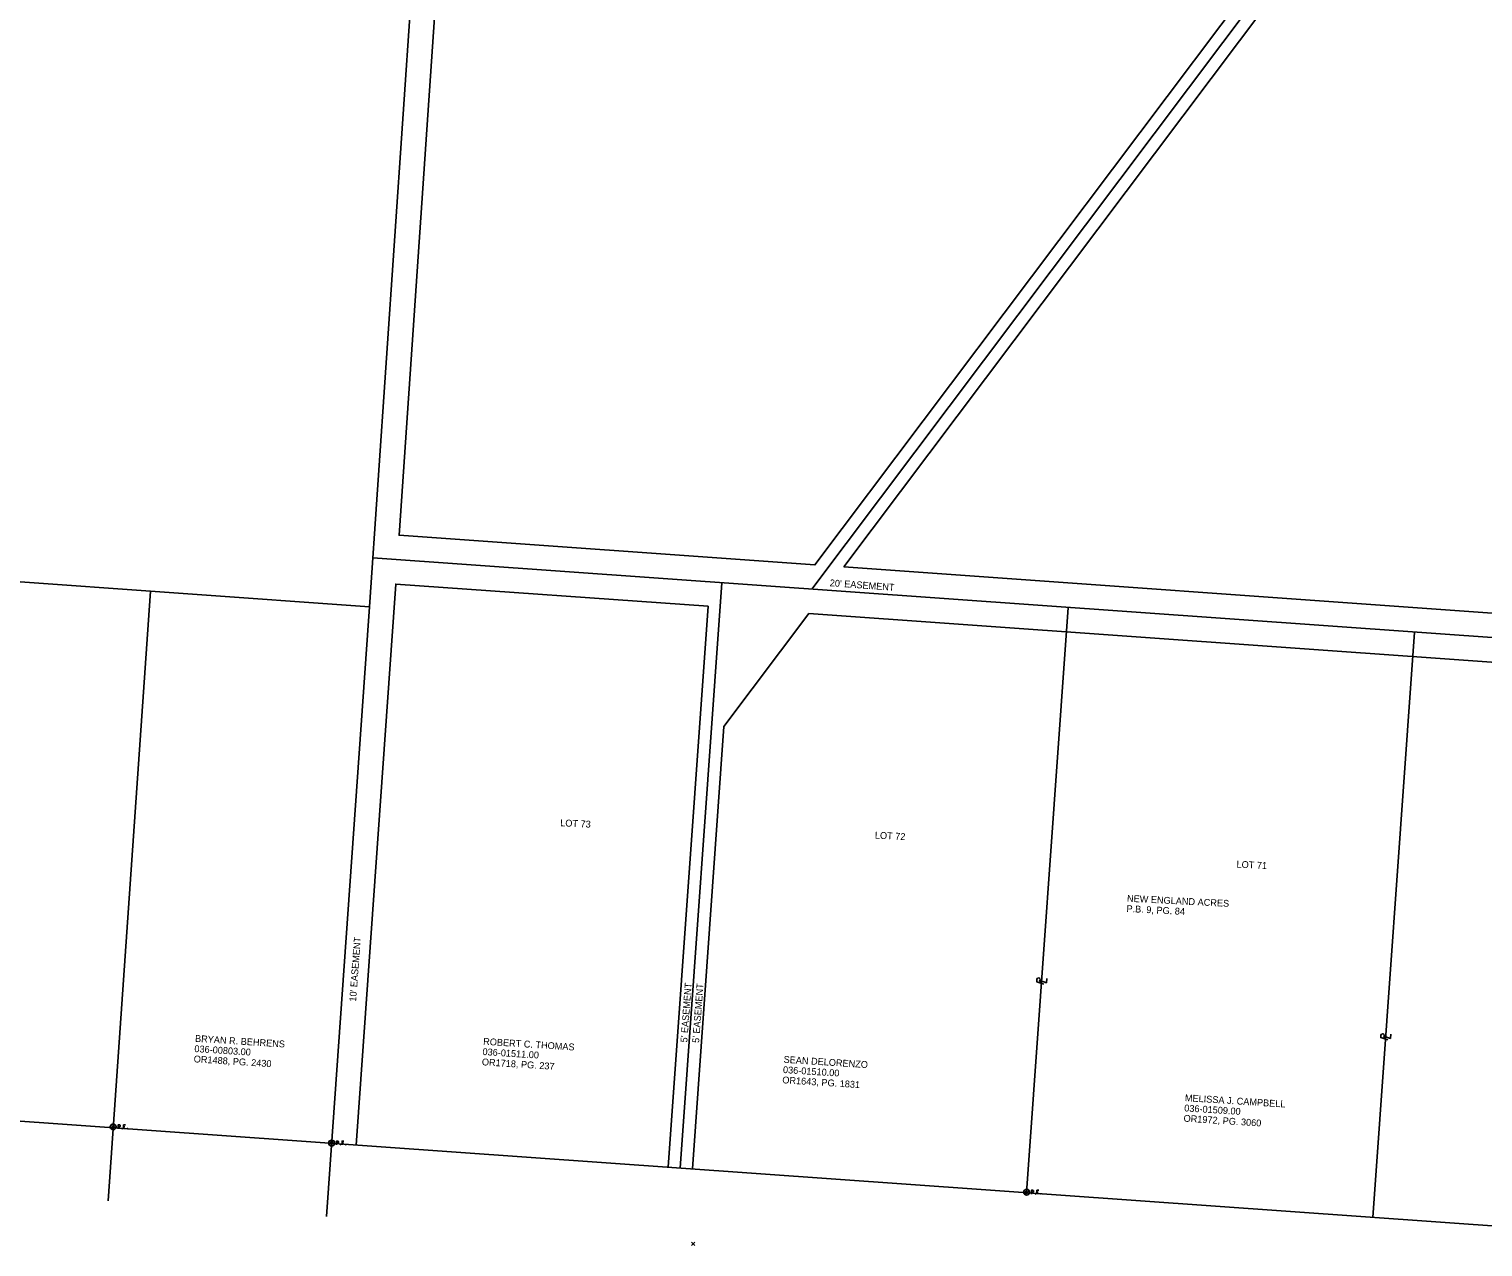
# Model space of a CAD drawing. Extents: x 1898254 to 1901377, y 701554 to 704886.
# Drawn here: x 1898855 to 1899450, y 703277 to 703775 of the extents above; entities that cross this region are included whole.
import ezdxf

# ---------------------------------------------------------------- set-up
doc = ezdxf.new("R2010")
doc.units = 0
for name, color, linetype in [('DV_X_Property_Line', 7, 'Continuous'), ('DV_X_Text', 7, 'Continuous'), ('RW_X_Esmt_General', 7, 'Continuous'), ('RW_X_Esmt_U', 7, 'Continuous'), ('RW_X_Fee_RW', 7, 'Continuous'), ('SC_Scratch2', 7, 'Continuous'), ('SC_Scratch5', 7, 'Continuous'), ('SV_X_Mon_Cells_Found', 7, 'Continuous'), ('SV_X_Random_Point', 7, 'Continuous')]:
    doc.layers.add(name, color=color, linetype=linetype)

msp = doc.modelspace()

# ---------------------------------------------------------------- linework, layer by layer
at = {"layer": 'DV_X_Property_Line'}
for p, q in [((1899357.75, 703788.77), (1899175.29, 703546.06)), ((1898994.39, 703538.88), (1898645.43, 703563.69)), ((1899563.1, 703518.49), (1898995.75, 703558.83)), ((1898887.4, 703295.86), (1898904.77, 703545.25)), ((1899138.49, 703548.68), (1899121.47, 703309.29)), ((1898994.39, 703538.88), (1898976.73, 703289.5)), ((1899280.14, 703538.61), (1899263.11, 703299.21)), ((1899421.78, 703528.54), (1899404.75, 703289.14)), ((1899268.59, 703385.02), (1899268.68, 703386.32)), ((1899269.27, 703385.78), (1899269.27, 703385.78)), ((1899409.33, 703362.22), (1899409.42, 703363.52)), ((1899410.01, 703362.98), (1899410.01, 703362.98))]:
    msp.add_line(p, q, dxfattribs=at)
for points in [[(1899270.15, 703384.49), (1899267.25, 703385.48), (1899267.32, 703386.51)], [(1899268.33, 703386.11), (1899271.22, 703385.11), (1899271.35, 703386.86)], [(1899410.88, 703361.69), (1899407.98, 703362.68), (1899408.06, 703363.71)], [(1899409.07, 703363.31), (1899411.96, 703362.31), (1899412.08, 703364.06)]]:
    msp.add_lwpolyline(points, dxfattribs=at)
for centre in [(1899267.99, 703386.36), (1899408.73, 703363.56)]:
    msp.add_arc(centre, 0.69, 356.4035, 167.26062, dxfattribs=at)
at = {"layer": 'DV_X_Text'}
msp.add_line((1899086.29, 704885.75), (1898994.39, 703538.88), dxfattribs=at)
at = {"layer": 'RW_X_Esmt_General'}
msp.add_line((1899139.33, 703489.9), (1899126.46, 703308.93), dxfattribs=at)
at = {"layer": 'RW_X_Esmt_U'}
for q in [(1899361.75, 703785.77), (1899563.81, 703528.46)]:
    msp.add_line((1899188.39, 703555.16), q, dxfattribs=at)
for points in [[(1899096.27, 704885.07), (1899006.4, 703568.1), (1899176.51, 703556), (1899353.75, 703791.78)], [(1898988.83, 703318.72), (1899005.04, 703548.15), (1899132.8, 703539.06), (1899116.48, 703309.64)], [(1899139.33, 703489.9), (1899174.08, 703536.13), (1899562.39, 703508.51)]]:
    msp.add_lwpolyline(points, dxfattribs=at)
at = {"layer": 'RW_X_Fee_RW'}
msp.add_line((1898630.14, 703344.22), (1899526.13, 703280.51), dxfattribs=at)
at = {"layer": 'SC_Scratch2'}
msp.add_circle((1899815.76, 703229.84), 1561.35, dxfattribs=at)
at = {"layer": 'SC_Scratch5'}
msp.add_line((1898630.14, 703344.22), (1899526.13, 703280.51), dxfattribs=at)
at = {"layer": 'SV_X_Mon_Cells_Found'}
for points in [[(1898891.51, 703325.34), (1898891.51, 703326.94), (1898892.04, 703326.94), (1898892.09, 703326.93), (1898892.17, 703326.91), (1898892.2, 703326.88), (1898892.24, 703326.86), (1898892.28, 703326.79), (1898892.31, 703326.73), (1898892.34, 703326.63), (1898892.34, 703326.48), (1898892.32, 703326.43), (1898892.3, 703326.35), (1898892.26, 703326.26), (1898892.21, 703326.23), (1898892.18, 703326.2), (1898892.13, 703326.18), (1898892.04, 703326.16), (1898891.51, 703326.16)], [(1898893.15, 703325.56), (1898893.21, 703325.56), (1898893.24, 703325.53), (1898893.27, 703325.48), (1898893.27, 703325.42), (1898893.24, 703325.37), (1898893.21, 703325.34), (1898893.15, 703325.34), (1898893.12, 703325.37), (1898893.09, 703325.42), (1898893.09, 703325.48), (1898893.12, 703325.53), (1898893.15, 703325.56)], [(1898894.52, 703326.94), (1898893.76, 703326.94), (1898893.76, 703325.34)], [(1898893.76, 703326.16), (1898894.3, 703326.16)], [(1898895.3, 703325.56), (1898895.36, 703325.56), (1898895.39, 703325.53), (1898895.42, 703325.48), (1898895.42, 703325.42), (1898895.39, 703325.37), (1898895.36, 703325.34), (1898895.3, 703325.34), (1898895.27, 703325.37), (1898895.23, 703325.42), (1898895.23, 703325.48), (1898895.27, 703325.53), (1898895.3, 703325.56)], [(1898980.86, 703318.73), (1898980.86, 703320.33), (1898981.39, 703320.33), (1898981.44, 703320.32), (1898981.52, 703320.29), (1898981.55, 703320.27), (1898981.58, 703320.24), (1898981.63, 703320.18), (1898981.66, 703320.12), (1898981.68, 703320.02), (1898981.68, 703319.87), (1898981.67, 703319.82), (1898981.65, 703319.74), (1898981.61, 703319.65), (1898981.56, 703319.61), (1898981.53, 703319.59), (1898981.47, 703319.56), (1898981.39, 703319.55), (1898980.86, 703319.55)], [(1898982.5, 703318.95), (1898982.56, 703318.95), (1898982.59, 703318.92), (1898982.62, 703318.87), (1898982.62, 703318.81), (1898982.59, 703318.76), (1898982.56, 703318.73), (1898982.5, 703318.73), (1898982.47, 703318.76), (1898982.43, 703318.81), (1898982.43, 703318.87), (1898982.47, 703318.92), (1898982.5, 703318.95)], [(1898983.87, 703320.33), (1898983.11, 703320.33), (1898983.11, 703318.73)], [(1898983.11, 703319.55), (1898983.65, 703319.55)], [(1898984.65, 703318.95), (1898984.7, 703318.95), (1898984.74, 703318.92), (1898984.77, 703318.87), (1898984.77, 703318.81), (1898984.74, 703318.76), (1898984.7, 703318.73), (1898984.65, 703318.73), (1898984.62, 703318.76), (1898984.58, 703318.81), (1898984.58, 703318.87), (1898984.62, 703318.92), (1898984.65, 703318.95)], [(1899265.12, 703298.62), (1899265.12, 703300.22), (1899265.65, 703300.22), (1899265.71, 703300.2), (1899265.79, 703300.18), (1899265.82, 703300.15), (1899265.85, 703300.13), (1899265.9, 703300.07), (1899265.93, 703300), (1899265.95, 703299.9), (1899265.95, 703299.75), (1899265.94, 703299.7), (1899265.92, 703299.62), (1899265.87, 703299.54), (1899265.83, 703299.5), (1899265.8, 703299.47), (1899265.74, 703299.45), (1899265.65, 703299.44), (1899265.12, 703299.44)], [(1899268.13, 703300.22), (1899267.37, 703300.22), (1899267.37, 703298.62)], [(1899267.37, 703299.44), (1899267.91, 703299.44)], [(1899266.77, 703298.83), (1899266.82, 703298.83), (1899266.85, 703298.81), (1899266.89, 703298.76), (1899266.89, 703298.69), (1899266.85, 703298.64), (1899266.82, 703298.62), (1899266.77, 703298.62), (1899266.73, 703298.64), (1899266.7, 703298.69), (1899266.7, 703298.76), (1899266.73, 703298.81), (1899266.77, 703298.83)], [(1899268.92, 703298.83), (1899268.97, 703298.83), (1899269, 703298.81), (1899269.04, 703298.76), (1899269.04, 703298.69), (1899269, 703298.64), (1899268.97, 703298.62), (1899268.92, 703298.62), (1899268.88, 703298.64), (1899268.85, 703298.69), (1899268.85, 703298.76), (1899268.88, 703298.81), (1899268.92, 703298.83)]]:
    msp.add_lwpolyline(points, dxfattribs=at)
for centre, radius in [((1898889.51, 703326.14), 1.2), ((1898889.51, 703326.14), 0.495), ((1898978.86, 703319.53), 1.2), ((1898978.86, 703319.53), 0.495), ((1899263.13, 703299.42), 1.2), ((1899263.13, 703299.42), 0.495)]:
    msp.add_circle(centre, radius, dxfattribs=at)
at = {"layer": 'SV_X_Random_Point'}
for p, q in [((1899126.06, 703277.65), (1899127.39, 703278.99)), ((1899126.06, 703278.99), (1899127.39, 703277.65))]:
    msp.add_line(p, q, dxfattribs=at)

# ---------------------------------------------------------------- texts
at = {"layer": 'DV_X_Text'}
for s, rotation, p in [("20' EASEMENT ", 355.93252, (1899182.53, 703547.3)), ('LOT 73', 357.09486, (1899072.29, 703449.16)), ('LOT 72', 357.09486, (1899201.01, 703444.09)), ('LOT 71', 357.09486, (1899348.95, 703432.21)), ('NEW ENGLAND ACRES', 357.09486, (1899304.14, 703418.24)), ('P.B. 9, PG. 84', 357.09486, (1899303.93, 703414.05)), ("10' EASEMENT ", 85.7139, (1898988.83, 703377.29)), ("5' EASEMENT ", 85.7139, (1899124.31, 703360.6)), ("5' EASEMENT ", 85.7139, (1899129.14, 703360.4)), ('036-00803.00', 356.3351, (1898922.63, 703356.77)), ('BRYAN R. BEHRENS', 356.3351, (1898922.9, 703360.96)), ('ROBERT C. THOMAS', 356.3351, (1899040.76, 703359.75)), ('OR1488, PG. 2430', 356.3351, (1898922.36, 703352.58)), ('OR1718, PG. 237', 356.3351, (1899040.23, 703351.36)), ('036-01511.00', 356.3351, (1899040.49, 703355.55)), ('SEAN DELORENZO', 356.3351, (1899163.66, 703352.39)), ('OR1643, PG. 1831', 356.3351, (1899163.13, 703344)), ('036-01510.00', 356.3351, (1899163.4, 703348.19)), ('036-01509.00', 356.3351, (1899327.54, 703332.5)), ('MELISSA J. CAMPBELL', 356.3351, (1899327.81, 703336.69)), ('OR1972, PG. 3060', 356.3351, (1899327.27, 703328.31))]:
    msp.add_text(s, height=2.8, rotation=rotation, dxfattribs=at).set_placement(p)

doc.saveas('drawing.dxf')
